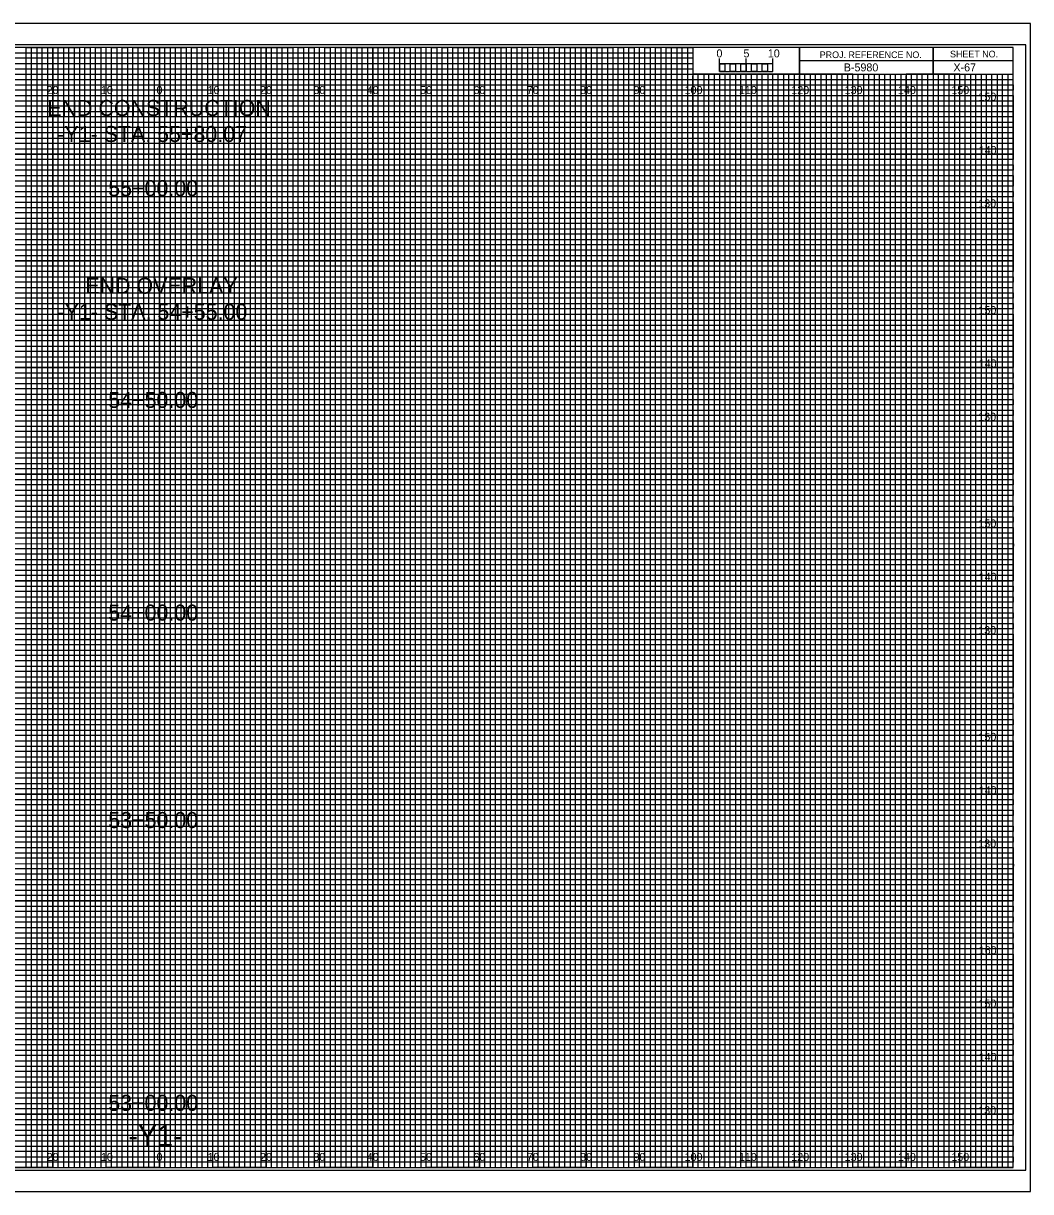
# Model space of a CAD drawing. Extents: x -13 to 323, y -5 to 4834.
# Drawn here: x 134.5 to 323.3, y 4615.5 to 4834.5 of the extents above; entities that cross this region are included whole.
import ezdxf

# ---------------------------------------------------------------- set-up
doc = ezdxf.new("R2010")
doc.units = 0
for name, color, linetype in [('Exist CMT Pavement', 7, 'Continuous'), ('Exist Cross Section Cell', 7, 'Continuous'), ('Exist XS Center Line Elevation Label', 7, 'Continuous'), ('Exist XS Ground Line', 7, 'Continuous'), ('Prop CMT Pvmt Course 1', 7, 'Continuous'), ('Prop CMT Pvmt Course 1 Wedge', 7, 'Continuous'), ('Prop CMT Pvmt Course 2', 7, 'Continuous'), ('Prop CMT Pvmt Course 2 Wedge', 7, 'Continuous'), ('Prop CMT Pvmt Course 3', 7, 'Continuous'), ('Prop CMT Pvmt Course 3 Wedge', 7, 'Continuous'), ('Prop CMT Pvmt Surface', 7, 'Continuous'), ('Prop CMT Pvmt Surface Shoulder', 7, 'Continuous'), ('Prop CMT Shld Paved Course 1', 7, 'Continuous'), ('Prop CMT Shld Paved Course 2', 7, 'Continuous'), ('Prop CMT Shld Paved Course 3', 7, 'Continuous'), ('Prop CMT Slope Grass', 7, 'Continuous'), ('Prop CMT Subgrade Earthwork', 7, 'Continuous')]:
    doc.layers.add(name, color=color, linetype=linetype)

msp = doc.modelspace()

# ---------------------------------------------------------------- linework, layer by layer
at = {"layer": 'Exist XS Center Line Elevation Label'}
for points in [[(125, 4620), (135, 4620), (135, 4830), (145, 4830), (145, 4620), (155, 4620), (155, 4830), (165, 4830), (165, 4620), (175, 4620), (175, 4830), (185, 4830), (185, 4620), (195, 4620), (195, 4830), (205, 4830), (205, 4620), (215, 4620), (215, 4830), (225, 4830), (225, 4620), (235, 4620), (235, 4830), (245, 4830), (245, 4620), (255, 4620), (255, 4830), (259.93, 4830), (260, 4830), (260, 4825), (264.99, 4825), (264.99, 4620), (275, 4620), (275, 4825), (285, 4825), (285, 4620), (295, 4620), (295, 4825), (305, 4825), (305, 4620), (315, 4620), (315, 4825)], [(0, 4825), (275, 4825)], [(0, 4805), (320, 4805), (320, 4815), (0, 4815)], [(0, 4785), (320, 4785), (320, 4795), (0, 4795)], [(0, 4765), (320, 4765), (320, 4775), (0, 4775)], [(0, 4745), (320, 4745), (320, 4755), (0, 4755)], [(0, 4725), (320, 4725), (320, 4735), (0, 4735)], [(0, 4705), (320, 4705), (320, 4715), (0, 4715)], [(0, 4685), (320, 4685), (320, 4695), (0, 4695)], [(0, 4665), (320, 4665), (320, 4675), (0, 4675)], [(0, 4645), (320, 4645), (320, 4655), (0, 4655)], [(0, 4625), (320, 4625), (320, 4635), (0, 4635)]]:
    msp.add_lwpolyline(points, dxfattribs=at)
at = {"layer": 'Exist XS Ground Line'}
for p, q in [((150, 4830), (140, 4830)), ((140, 4830), (140, 4620)), ((150, 4620), (150, 4830)), ((170, 4830), (160, 4830)), ((160, 4830), (160, 4620)), ((170, 4620), (170, 4830)), ((190, 4830), (180, 4830)), ((180, 4830), (180, 4620)), ((190, 4620), (190, 4830)), ((210, 4830), (200, 4830)), ((200, 4830), (200, 4620)), ((210, 4620), (210, 4830)), ((230, 4830), (220, 4830)), ((220, 4830), (220, 4620)), ((230, 4620), (230, 4830)), ((250, 4830), (240, 4830)), ((240, 4830), (240, 4620)), ((250, 4620), (250, 4830)), ((260, 4830), (260, 4620)), ((270, 4620), (270, 4825)), ((290, 4825), (280, 4825)), ((280, 4825), (280, 4620)), ((290, 4620), (290, 4825)), ((310, 4825), (300, 4825)), ((300, 4825), (300, 4620)), ((310, 4620), (310, 4825)), ((140, 4620), (130, 4620)), ((160, 4620), (150, 4620)), ((180, 4620), (170, 4620)), ((200, 4620), (190, 4620)), ((220, 4620), (210, 4620)), ((240, 4620), (230, 4620)), ((260, 4620), (250, 4620)), ((280, 4620), (270, 4620)), ((300, 4620), (290, 4620)), ((320, 4620), (310, 4620)), ((320, 4620), (320, 4620))]:
    msp.add_line(p, q, dxfattribs=at)
for points in [[(0, 4820), (320, 4820), (320, 4810), (0, 4810)], [(0, 4800), (320, 4800), (320, 4790), (0, 4790)], [(0, 4780), (320, 4780), (320, 4770), (0, 4770)], [(0, 4760), (320, 4760), (320, 4750), (0, 4750)], [(0, 4740), (320, 4740), (320, 4730), (0, 4730)], [(0, 4720), (320, 4720), (320, 4710), (0, 4710)], [(0, 4700), (320, 4700), (320, 4690), (0, 4690)], [(0, 4680), (320, 4680), (320, 4670), (0, 4670)], [(0, 4660), (320, 4660), (320, 4650), (0, 4650)], [(0, 4640), (320, 4640), (320, 4630), (0, 4630)]]:
    msp.add_lwpolyline(points, dxfattribs=at)
at = {"layer": 'Prop CMT Pvmt Course 1'}
for p, q in [((267, 4825), (266.01, 4825)), ((266.01, 4825), (266.01, 4620)), ((267, 4620), (267, 4825)), ((269, 4825), (268, 4825)), ((268, 4825), (268, 4620)), ((269, 4620), (269, 4825)), ((266.01, 4620), (265, 4620)), ((268, 4620), (267, 4620))]:
    msp.add_line(p, q, dxfattribs=at)
for points in [[(135, 4620), (136, 4620), (136, 4830), (137, 4830), (137, 4620)], [(137, 4620), (138, 4620), (138, 4830), (139, 4830), (139, 4620)], [(140, 4620), (141, 4620), (141, 4830), (142, 4830), (142, 4620)], [(142, 4620), (143, 4620), (143, 4830), (144, 4830), (144, 4620)], [(145, 4620), (146, 4620), (146, 4830), (147, 4830), (147, 4620)], [(147, 4620), (148, 4620), (148, 4830), (149, 4830), (149, 4620)], [(150, 4620), (151, 4620), (151, 4830), (152, 4830), (152, 4620)], [(152, 4620), (153, 4620), (153, 4830), (154, 4830), (154, 4620)], [(155, 4620), (156, 4620), (156, 4830), (157, 4830), (157, 4620)], [(157, 4620), (158, 4620), (158, 4830), (159, 4830), (159, 4620)], [(160, 4620), (161, 4620), (161, 4830), (162, 4830), (162, 4620)], [(162, 4620), (163, 4620), (163, 4830), (164, 4830), (164, 4620)], [(165, 4620), (166, 4620), (166, 4830), (167, 4830), (167, 4620)], [(167, 4620), (168, 4620), (168, 4830), (169, 4830), (169, 4620)], [(170, 4620), (171, 4620), (171, 4830), (172, 4830), (172, 4620)], [(172, 4620), (173, 4620), (173, 4830), (174, 4830), (174, 4620)], [(175, 4620), (176, 4620), (176, 4830), (177, 4830), (177, 4620)], [(177, 4620), (178, 4620), (178, 4830), (179, 4830), (179, 4620)], [(180, 4620), (181, 4620), (181, 4830), (182, 4830), (182, 4620)], [(182, 4620), (183, 4620), (183, 4830), (184, 4830), (184, 4620)], [(185, 4620), (186, 4620), (186, 4830), (187, 4830), (187, 4620)], [(187, 4620), (188, 4620), (188, 4830), (189, 4830), (189, 4620)], [(190, 4620), (191, 4620), (191, 4830), (192, 4830), (192, 4620)], [(192, 4620), (193, 4620), (193, 4830), (194, 4830), (194, 4620)], [(195, 4620), (196, 4620), (196, 4830), (197, 4830), (197, 4620)], [(197, 4620), (198, 4620), (198, 4830), (199, 4830), (199, 4620)], [(200, 4620), (201, 4620), (201, 4830), (202, 4830), (202, 4620)], [(202, 4620), (203, 4620), (203, 4830), (204, 4830), (204, 4620)], [(205, 4620), (206, 4620), (206, 4830), (207, 4830), (207, 4620)], [(207, 4620), (208, 4620), (208, 4830), (209, 4830), (209, 4620)], [(210, 4620), (211, 4620), (211, 4830), (212, 4830), (212, 4620)], [(212, 4620), (213, 4620), (213, 4830), (214, 4830), (214, 4620)], [(215, 4620), (216, 4620), (216, 4830), (217, 4830), (217, 4620)], [(217, 4620), (218, 4620), (218, 4830), (219, 4830), (219, 4620)], [(220, 4620), (221, 4620), (221, 4830), (222, 4830), (222, 4620)], [(222, 4620), (223, 4620), (223, 4830), (224, 4830), (224, 4620)], [(225, 4620), (226, 4620), (226, 4830), (227, 4830), (227, 4620)], [(227, 4620), (228, 4620), (228, 4830), (229, 4830), (229, 4620)], [(230, 4620), (231, 4620), (231, 4830), (232, 4830), (232, 4620)], [(232, 4620), (233, 4620), (233, 4830), (234, 4830), (234, 4620)], [(235, 4620), (236, 4620), (236, 4830), (237, 4830), (237, 4620)], [(237, 4620), (238, 4620), (238, 4830), (239, 4830), (239, 4620)], [(240, 4620), (241, 4620), (241, 4830), (242, 4830), (242, 4620)], [(242, 4620), (243, 4620), (243, 4830), (244, 4830), (244, 4620)], [(245, 4620), (246, 4620), (246, 4830), (247, 4830), (247, 4620)], [(247, 4620), (248, 4620), (248, 4830), (249, 4830), (249, 4620)], [(250, 4620), (251, 4620), (251, 4830), (252, 4830), (252, 4620)], [(252, 4620), (253, 4620), (253, 4830), (254, 4830), (254, 4620)], [(255, 4620), (256, 4620), (256, 4830), (257, 4830), (257, 4620)], [(257, 4620), (258, 4620), (258, 4830), (259, 4830), (259, 4620)], [(260, 4620), (261, 4620), (261, 4825), (262.02, 4825), (262.02, 4620)], [(262, 4620), (263, 4620), (263, 4825), (263.99, 4825), (263.99, 4620)], [(270, 4620), (270.98, 4620), (270.98, 4825), (272, 4825), (272, 4620)], [(272, 4620), (273, 4620), (273, 4825), (274.05, 4825), (274.05, 4620)], [(275, 4620), (276, 4620), (276, 4825), (277, 4825), (277, 4620)], [(277, 4620), (278, 4620), (278, 4825), (279, 4825), (279, 4620)], [(280, 4620), (281, 4620), (281, 4825), (282, 4825), (282, 4620)], [(282, 4620), (283, 4620), (283, 4825), (284, 4825), (284, 4620)], [(285, 4620), (286, 4620), (286, 4825), (287, 4825), (287, 4620)], [(287, 4620), (288, 4620), (288, 4825), (289, 4825), (289, 4620)], [(290, 4620), (291, 4620), (291, 4825), (292, 4825), (292, 4620)], [(292, 4620), (293, 4620), (293, 4825), (294, 4825), (294, 4620)], [(295, 4620), (296, 4620), (296, 4825), (297, 4825), (297, 4620)], [(297, 4620), (298, 4620), (298, 4825), (299, 4825), (299, 4620)], [(300, 4620), (301, 4620), (301, 4825), (302, 4825), (302, 4620)], [(302, 4620), (303, 4620), (303, 4825), (304, 4825), (304, 4620)], [(305, 4620), (306, 4620), (306, 4825), (307, 4825), (307, 4620)], [(307, 4620), (308, 4620), (308, 4825), (309, 4825), (309, 4620)], [(310, 4620), (311, 4620), (311, 4825), (312, 4825), (312, 4620)], [(312, 4620), (313, 4620), (313, 4825), (314, 4825), (314, 4620)], [(315, 4620), (316, 4620), (316, 4825), (317, 4825), (317, 4620)], [(317, 4620), (318, 4620), (318, 4825), (319, 4825), (319, 4620)]]:
    msp.add_lwpolyline(points, dxfattribs=at)
at = {"layer": 'Prop CMT Pvmt Course 2'}
for p, q in [((323.3, 4834.5), (-13.4, 4834.5)), ((-13.4, 4615.5), (323.3, 4615.5))]:
    msp.add_line(p, q, dxfattribs=at)
at = {"layer": 'Prop CMT Pvmt Surface Shoulder'}
for p, q in [((305, 4830), (305, 4825)), ((305, 4825), (305, 4830)), ((280, 4827.5), (280, 4825)), ((320, 4827.49), (280, 4827.49)), ((280, 4825), (320, 4825))]:
    msp.add_line(p, q, dxfattribs=at)
for points in [[(320, 4830), (0, 4830), (0, 4620), (320, 4620)], [(280, 4830), (260, 4830), (260, 4825.03), (280, 4825.03)], [(320, 4830), (280, 4830), (280, 4825), (320, 4825)]]:
    msp.add_lwpolyline(points, close=True, dxfattribs=at)
at = {"layer": 'Prop CMT Shld Paved Course 1'}
msp.add_lwpolyline([(-13.4, 4615.5), (323.3, 4615.5), (323.3, 4834.5), (-13.4, 4834.5)], close=True, dxfattribs=at)
at = {"layer": 'Prop CMT Shld Paved Course 2'}
msp.add_lwpolyline([(-10.8, 4619.5), (322.4, 4619.5), (322.4, 4830.5), (-10.8, 4830.5)], close=True, dxfattribs=at)
at = {"layer": 'Prop CMT Shld Paved Course 3'}
for p, q in [((140, 4620), (140, 4830)), ((150, 4620), (150, 4830)), ((160, 4620), (160, 4830)), ((170, 4620), (170, 4830)), ((180, 4620), (180, 4830)), ((190, 4620), (190, 4830)), ((200, 4620), (200, 4830)), ((210, 4620), (210, 4830)), ((220, 4620), (220, 4830)), ((230, 4620), (230, 4830)), ((240, 4620), (240, 4830)), ((250, 4620), (250, 4830)), ((260, 4620), (260, 4824.69)), ((270, 4620), (270, 4824.69)), ((280, 4620), (280, 4824.69)), ((290, 4620), (290, 4824.69)), ((300, 4620), (300, 4824.69)), ((310, 4620), (310, 4824.69)), ((0, 4820), (320, 4820)), ((0, 4810), (320, 4810)), ((0, 4800), (320, 4800)), ((0, 4790), (320, 4790)), ((0, 4780), (320, 4780)), ((0, 4770), (320, 4770)), ((0, 4760), (320, 4760)), ((0, 4750), (320, 4750)), ((0, 4740), (320, 4740)), ((0, 4730), (320, 4730)), ((0, 4720), (320, 4720)), ((0, 4710), (320, 4710)), ((0, 4700), (320, 4700)), ((0, 4690), (320, 4690)), ((0, 4680), (320, 4680)), ((0, 4670), (320, 4670)), ((0, 4660), (320, 4660)), ((0, 4650), (320, 4650)), ((0, 4640), (320, 4640)), ((0, 4630), (320, 4630))]:
    msp.add_line(p, q, dxfattribs=at)
at = {"layer": 'Prop CMT Slope Grass'}
for p, q in [((0, 4829), (260, 4829)), ((260, 4829), (260, 4827.98)), ((260, 4827.98), (0, 4827.98)), ((0, 4827), (260, 4827)), ((260, 4827), (260, 4825.89)), ((260, 4825.89), (0, 4825.89)), ((0, 4824), (320, 4824))]:
    msp.add_line(p, q, dxfattribs=at)
for points in [[(0, 4823), (270, 4823), (320, 4823), (320, 4822), (0, 4822)], [(0, 4821), (320, 4821), (320, 4819), (0, 4819)], [(0, 4818), (320, 4818), (320, 4817), (0, 4816.98)], [(0, 4816), (320, 4816), (320, 4814), (0, 4814)], [(0, 4813), (320, 4813), (320, 4812), (0, 4812)], [(0, 4811), (320, 4811), (320, 4809), (0, 4809)], [(0, 4808), (320, 4808), (320, 4807), (0, 4807)], [(0, 4806), (320, 4806), (320, 4804), (0, 4804)], [(0, 4803), (320, 4803), (320, 4802), (0, 4802)], [(0, 4801), (320, 4801), (320, 4799), (0, 4799)], [(0, 4798), (320, 4798), (320, 4797), (0, 4797)], [(0, 4796), (320, 4796), (320, 4793.95), (320, 4793), (320, 4792), (0, 4792)], [(0, 4794), (320, 4794), (320, 4793), (0, 4793)], [(0, 4791), (320, 4791), (320, 4789), (0, 4789.03)], [(0, 4789.03), (320, 4789), (320, 4788), (0, 4788)], [(0, 4787), (320, 4787), (320, 4786), (0, 4786)], [(0, 4784), (320, 4784), (320, 4783), (0, 4783)], [(0, 4782), (320, 4782), (320, 4781), (0, 4781)], [(-0.07, 4778.89), (320, 4778.89), (320, 4777.88), (-0.07, 4777.88)], [(0, 4777), (320, 4777), (320, 4776), (0, 4776)], [(0, 4774), (320, 4774), (320, 4773), (0, 4773)], [(0, 4772), (320, 4772), (320, 4771), (0, 4771)], [(0, 4769), (320, 4769), (320, 4768), (0, 4768)], [(0, 4767), (320, 4767), (320, 4766), (0, 4766)], [(0, 4764), (320, 4764), (320, 4763), (0, 4763)], [(0, 4762), (320, 4762), (320, 4761), (0, 4761)], [(0, 4759), (320, 4759), (319.99, 4757.98), (0, 4758)], [(0, 4757), (320, 4757), (320, 4756), (0, 4756)], [(0, 4754), (320, 4754), (320, 4753), (0, 4753)], [(0, 4752), (320, 4752), (320, 4751), (0, 4751)], [(0, 4749), (320, 4749), (320, 4748), (0, 4748)], [(0, 4747), (320, 4747), (320, 4746), (0, 4746)], [(0, 4744), (320, 4744), (320, 4743), (0, 4743)], [(0, 4742), (320, 4742), (320, 4741), (0, 4741)], [(0, 4739), (320, 4739), (320, 4738), (0, 4738)], [(0, 4736.99), (320.07, 4736.91), (320, 4736), (0, 4736)], [(0, 4734), (320, 4734), (320, 4733), (0, 4733)], [(0, 4732), (320, 4732), (320, 4731), (0, 4731)], [(0, 4729), (320, 4729), (320, 4728), (0, 4728)], [(0, 4727), (320, 4727), (320, 4726), (0, 4726)], [(0, 4724), (320, 4724), (320, 4723), (0, 4723)], [(0, 4722), (320, 4722), (320, 4721), (0, 4721)], [(0, 4719), (320, 4719), (320, 4718), (0, 4718)], [(0, 4717), (320, 4717), (320, 4716), (0, 4716)], [(0, 4714), (320, 4714), (320, 4713), (0, 4713)], [(0, 4712), (320, 4712), (320, 4711), (0, 4711)], [(0, 4709), (320, 4709), (320, 4708), (0, 4708)], [(0, 4707), (320, 4707), (320, 4706), (0, 4706)], [(0, 4704), (320, 4704), (320, 4703), (0, 4703)], [(0, 4702), (320, 4702), (320, 4701), (0, 4701)], [(0, 4699), (320, 4699), (319.99, 4697.98), (0, 4698)], [(0, 4697), (320, 4697), (320, 4696), (0, 4696)], [(0, 4694), (320, 4694), (320, 4693), (0, 4693)], [(0, 4692), (320, 4692), (320, 4691), (0, 4691)], [(0, 4689), (320, 4689), (320, 4688), (0, 4688)], [(0, 4687), (320, 4687), (320, 4686), (0, 4686)], [(0, 4684), (320, 4684), (320, 4683), (0, 4683)], [(0, 4682), (320, 4682), (320, 4681), (0, 4681)], [(0, 4679), (320, 4679), (320, 4678), (0, 4678)], [(0, 4676.99), (320.07, 4676.91), (320, 4676), (0, 4676)], [(0, 4674), (320, 4674), (320, 4673), (0, 4673)], [(0, 4672), (320, 4672), (320, 4671), (0, 4671)], [(0, 4669), (320, 4669), (320, 4668), (0, 4668)], [(0, 4667), (320, 4667), (320, 4666), (0, 4666)], [(0, 4664), (320, 4664), (320, 4663), (0, 4663)], [(0, 4662), (320, 4662), (320, 4661), (0, 4661)], [(0, 4659), (320, 4659), (320, 4658), (0, 4658)], [(0, 4657), (320, 4657), (320, 4656), (0, 4656)], [(0, 4654), (320, 4654), (320, 4653), (0, 4653)], [(0, 4652), (320, 4652), (320, 4651), (0, 4651)], [(0, 4649), (320, 4649), (320, 4648), (0, 4648)], [(0, 4647), (320, 4647), (320, 4646), (0, 4646)], [(0, 4644), (320, 4644), (320, 4643), (0, 4643)], [(0, 4642), (320, 4642), (320, 4641), (0, 4641)], [(0, 4639), (320, 4639), (320, 4638), (0, 4638)], [(0, 4637), (320, 4637), (320, 4636), (0, 4636)], [(0, 4634), (320, 4634), (320, 4633), (0, 4633)], [(0, 4632), (320, 4632), (320, 4631), (0, 4631)], [(0, 4629), (320, 4629), (320, 4628), (0, 4628)], [(0, 4627), (320, 4627), (320, 4626), (0, 4626)], [(0, 4624), (320, 4624), (320, 4623), (0, 4623)], [(0, 4622), (320, 4622), (320, 4621), (0, 4621)]]:
    msp.add_lwpolyline(points, dxfattribs=at)
at = {"layer": 'Prop CMT Subgrade Earthwork'}
for p, q in [((265, 4825.49), (265, 4827.9)), ((265, 4826.9), (265, 4827.9)), ((270, 4825.49), (270, 4827.9)), ((275, 4825.49), (275, 4827.9)), ((275, 4826.9), (275, 4827.9))]:
    msp.add_line(p, q, dxfattribs=at)
for points in [[(275, 4826.9), (265, 4826.9), (265, 4825.49), (275, 4825.49)], [(265, 4826.9), (266, 4826.9), (266, 4825.49), (265, 4825.49)], [(267, 4826.9), (268, 4826.9), (268, 4825.49), (267, 4825.49)], [(269, 4826.9), (270, 4826.9), (270, 4825.49), (269, 4825.49)], [(271, 4826.9), (272, 4826.9), (272, 4825.49), (271, 4825.49)], [(273, 4826.9), (274, 4826.9), (274, 4825.49), (273, 4825.49)]]:
    msp.add_lwpolyline(points, close=True, dxfattribs=at)

# ---------------------------------------------------------------- texts
at = {"layer": 'Exist CMT Pavement'}
msp.add_text('-Y1-', height=4, dxfattribs=at).set_placement((154.21, 4624))
at = {"layer": 'Exist Cross Section Cell'}
for s, p in [('20', (138.86, 4821.25)), ('10', (149.04, 4821.25)), ('0', (159.45, 4821.25)), ('0', (159.45, 4821.25)), ('10', (169.04, 4821.25)), ('20', (178.86, 4821.25)), ('30', (188.86, 4821.25)), ('40', (198.86, 4821.25)), ('50', (208.86, 4821.25)), ('60', (218.86, 4821.25)), ('70', (228.86, 4821.25)), ('80', (238.86, 4821.25)), ('90', (248.86, 4821.25)), ('100', (258.44, 4821.25)), ('110', (268.62, 4821.25)), ('120', (278.44, 4821.25)), ('130', (288.44, 4821.25)), ('140', (298.44, 4821.25)), ('150', (308.44, 4821.25)), ('20', (138.86, 4621.25)), ('10', (149.04, 4621.25)), ('0', (159.45, 4621.25)), ('0', (159.45, 4621.25)), ('10', (169.04, 4621.25)), ('20', (178.86, 4621.25)), ('30', (188.86, 4621.25)), ('40', (198.86, 4621.25)), ('50', (208.86, 4621.25)), ('60', (218.86, 4621.25)), ('70', (228.86, 4621.25)), ('80', (238.86, 4621.25)), ('90', (248.86, 4621.25)), ('100', (258.44, 4621.25)), ('110', (268.62, 4621.25)), ('120', (278.44, 4621.25)), ('130', (288.44, 4621.25)), ('140', (298.44, 4621.25)), ('150', (308.44, 4621.25))]:
    msp.add_text(s, height=1.5, dxfattribs=at).set_placement(p)
at = {"layer": 'Prop CMT Pvmt Course 1 Wedge'}
for s, p in [('END CONSTRUCTION', (138.99, 4817.14)), ('-Y1- STA. 55+80.07', (140.85, 4812.26)), ('55+00.00', (150.41, 4802.1)), ('END OVERLAY', (146.12, 4783.81)), ('-Y1- STA. 54+55.00', (140.91, 4778.94)), ('54+50.00', (150.41, 4762.41)), ('54+00.00', (150.41, 4722.54)), ('53+50.00', (150.41, 4683.66)), ('53+00.00', (150.41, 4630.64))]:
    msp.add_text(s, height=3, dxfattribs=at).set_placement(p)
at = {"layer": 'Prop CMT Pvmt Course 2 Wedge'}
msp.add_text('X-67', height=1.5, dxfattribs=at).set_placement((308.83, 4825.5))
at = {"layer": 'Prop CMT Pvmt Course 3'}
for s, p in [('150', (313.52, 4820)), ('140', (313.57, 4810)), ('130', (313.49, 4800)), ('150', (313.52, 4780)), ('140', (313.57, 4770)), ('130', (313.49, 4760)), ('150', (313.52, 4740)), ('140', (313.57, 4730)), ('130', (313.49, 4720)), ('150', (313.52, 4700)), ('140', (313.57, 4690)), ('130', (313.49, 4680)), ('160', (313.57, 4660)), ('150', (313.52, 4650)), ('140', (313.57, 4640)), ('130', (313.49, 4630))]:
    msp.add_text(s, height=1.5, dxfattribs=at).set_placement(p)
at = {"layer": 'Prop CMT Pvmt Course 3 Wedge'}
msp.add_text('B-5980', height=1.5, dxfattribs=at).set_placement((288.28, 4825.5))
at = {"layer": 'Prop CMT Pvmt Surface'}
for s, p in [('5', (269.47, 4828.12)), ('10', (274.04, 4828.12))]:
    msp.add_text(s, height=1.5, dxfattribs=at).set_placement(p)
at = {"layer": 'Prop CMT Pvmt Surface Shoulder'}
for s, p in [('PROJ. REFERENCE NO.', (283.77, 4827.99)), ('SHEET NO.', (308.19, 4828.12))]:
    msp.add_text(s, height=1.25, dxfattribs=at).set_placement(p)
at = {"layer": 'Prop CMT Subgrade Earthwork'}
msp.add_text('0', height=1.5, dxfattribs=at).set_placement((264.41, 4828.12))

doc.saveas('drawing.dxf')
